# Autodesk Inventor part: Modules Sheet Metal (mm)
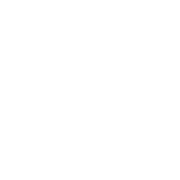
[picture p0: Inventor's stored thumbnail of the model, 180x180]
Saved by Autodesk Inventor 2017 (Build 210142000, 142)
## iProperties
Created: 2016-06
Part Number: Modules Sheet Metal (mm)
Material: Generic
Document SubType Name: Sheet Metal
Designer: Wally
Density: 1 g/cm^3
Sheet Metal Rule: Default
Appearance: Default
Author: Wally
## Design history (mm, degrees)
node "Sketch1"
other parameters: "Thickness" = 0.5, "BendRadius" = 0.5 (= Thickness), "BendReliefWidth" = 0.5 (= Thickness), "BendReliefDepth" = 0.25 (= 0.5 x Thickness), "CornerReliefSize" = 2 (= 4 x Thickness), "SeamGap" = 0.01, "MinimumRemnant" = 1 (= 2 x Thickness), "TransitionRadius" = 0.5 (= BendRadius), "JacobiRadiusSize" = 0.5 (= BendRadius), "GapSize" = 0.5 (= Thickness)
